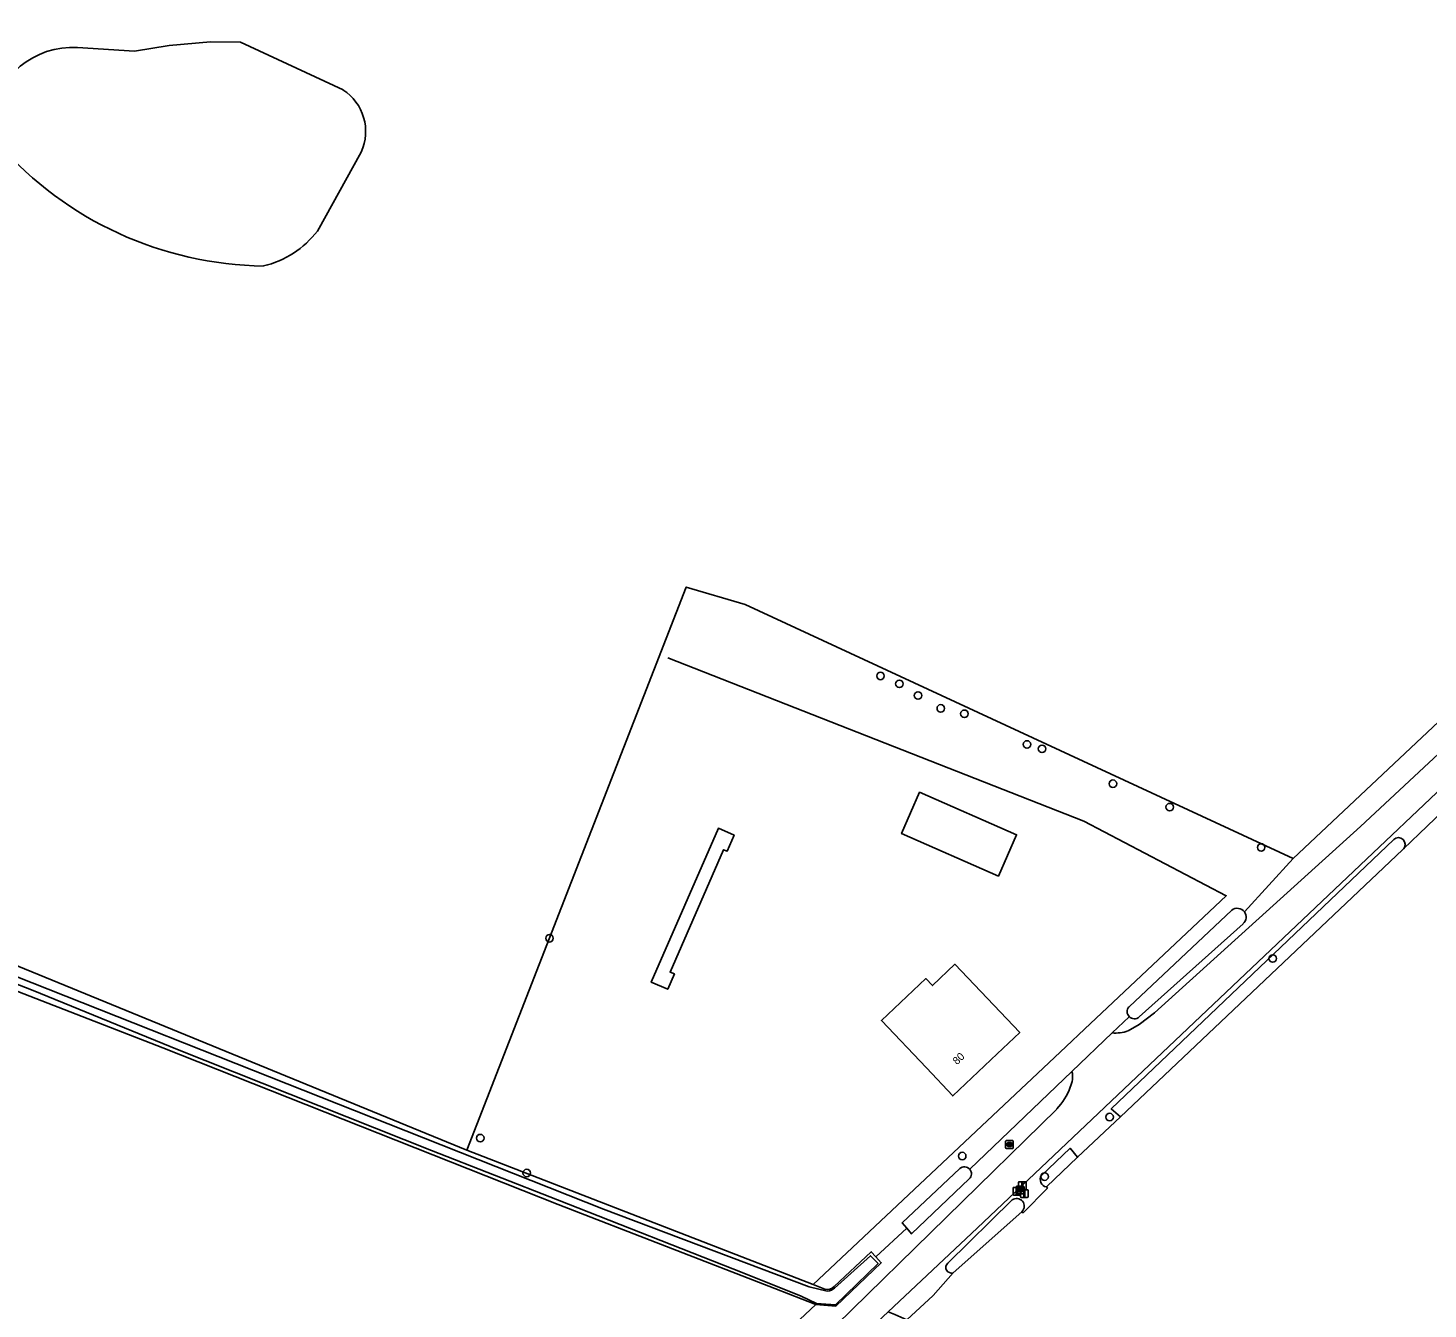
# Model space of a CAD drawing. Extents: x 155209 to 156748, y 385356 to 388487.
# Drawn here: x 155687.8 to 155870, y 387150.5 to 387317.3 of the extents above; entities that cross this region are included whole.
import ezdxf

# ---------------------------------------------------------------- set-up
doc = ezdxf.new("R2010")
doc.units = 0
for name, color, linetype in [('IMGEO_Afsluitpaal', 7, 'Continuous'), ('IMGEO_Berm_groen', 7, 'Continuous'), ('IMGEO_Boom', 7, 'Continuous'), ('IMGEO_Bouwland', 7, 'Continuous'), ('IMGEO_Brandkraan', 7, 'Continuous'), ('IMGEO_Erf', 7, 'Continuous'), ('IMGEO_Groenvoorziening', 7, 'Continuous'), ('IMGEO_Hek', 7, 'Continuous'), ('IMGEO_Meer_plas_ven_vijver', 7, 'Continuous'), ('IMGEO_Oever', 7, 'Continuous'), ('IMGEO_Pand', 7, 'Continuous'), ('IMGEO_Pand_nummerreeks', 7, 'Continuous'), ('IMGEO_Rijbaan_lokaal_onverhard', 7, 'Continuous'), ('IMGEO_Rioolput', 7, 'Continuous'), ('IMGEO_Waterloop', 7, 'Continuous')]:
    doc.layers.add(name, color=color, linetype=linetype)

msp = doc.modelspace()

# ---------------------------------------------------------------- linework, layer by layer
at = {"layer": 'IMGEO_Afsluitpaal'}
for p, q in [((155816.69, 387166.17), (155816.69, 387166.97)), ((155816.69, 387166.97), (155816.69, 387166.17)), ((155816.79, 387167.07), (155817.58, 387167.07)), ((155817.58, 387167.07), (155816.79, 387167.07)), ((155817.68, 387166.97), (155817.68, 387166.17)), ((155817.68, 387166.17), (155817.68, 387166.97)), ((155815.99, 387165.42), (155815.99, 387166.22)), ((155815.99, 387166.22), (155815.99, 387165.42)), ((155816.09, 387166.32), (155816.88, 387166.32)), ((155816.88, 387166.32), (155816.09, 387166.32)), ((155816.88, 387165.32), (155816.09, 387165.32)), ((155816.09, 387165.32), (155816.88, 387165.32)), ((155817.58, 387166.07), (155816.79, 387166.07)), ((155816.79, 387166.07), (155817.58, 387166.07)), ((155816.96, 387165.12), (155816.96, 387165.92)), ((155816.96, 387165.92), (155816.96, 387165.12)), ((155816.98, 387166.22), (155816.98, 387165.42)), ((155816.98, 387165.42), (155816.98, 387166.22)), ((155817.06, 387166.02), (155817.85, 387166.02)), ((155817.85, 387166.02), (155817.06, 387166.02)), ((155817.85, 387165.02), (155817.06, 387165.02)), ((155817.06, 387165.02), (155817.85, 387165.02)), ((155817.95, 387165.92), (155817.95, 387165.12)), ((155817.95, 387165.12), (155817.95, 387165.92))]:
    msp.add_line(p, q, dxfattribs=at)
for points in [[(155817.11, 387166.94), (155817.26, 387166.94), (155817.26, 387166.19), (155817.11, 387166.19), (155817.11, 387166.94)], [(155816.41, 387166.2), (155816.56, 387166.2), (155816.56, 387165.45), (155816.41, 387165.45), (155816.41, 387166.2)], [(155817.38, 387165.89), (155817.53, 387165.89), (155817.53, 387165.14), (155817.38, 387165.14), (155817.38, 387165.89)]]:
    msp.add_lwpolyline(points, dxfattribs=at)
for centre, start, end in [((155816.79, 387166.97), 90, 180), ((155816.79, 387166.97), 90, 180), ((155817.58, 387166.97), 0, 90), ((155817.58, 387166.97), 360, 90), ((155816.09, 387166.22), 90, 180), ((155816.09, 387166.22), 90, 180), ((155816.09, 387165.42), 180, 270), ((155816.09, 387165.42), 180, 270), ((155816.79, 387166.17), 180, 270), ((155816.79, 387166.17), 180, 270), ((155816.88, 387166.22), 0, 90), ((155816.88, 387166.22), 360, 90), ((155816.88, 387165.42), 270, 0), ((155816.88, 387165.42), 270, 0), ((155817.06, 387165.92), 90, 180), ((155817.06, 387165.92), 90, 180), ((155817.06, 387165.12), 180, 270), ((155817.06, 387165.12), 180, 270), ((155817.58, 387166.17), 270, 0), ((155817.58, 387166.17), 270, 0), ((155817.85, 387165.92), 0, 90), ((155817.85, 387165.92), 360, 90), ((155817.85, 387165.12), 270, 0), ((155817.85, 387165.12), 270, 0)]:
    msp.add_arc(centre, 0.1, start, end, dxfattribs=at)
at = {"layer": 'IMGEO_Berm_groen'}
for points in [[(155935.88, 387279.15), (155905.19, 387250), (155811.33, 387161.02), (155799.75, 387150.14), (155800.58, 387149.78), (155802.15, 387149.1), (155805.58, 387152.26), (155808.2, 387155.21)], [(155866.82, 387210.39), (155872.95, 387216.32), (155876.05, 387219.32)], [(155819.67, 387167.86), (155823.41, 387171.43), (155824.39, 387170.24), (155829.99, 387175.53), (155828.77, 387176.55), (155865.53, 387211.63)], [(155823.65, 387181.42), (155810.35, 387168.68)], [(155756.84, 387113.86), (155783.96, 387139.94), (155792.97, 387148.4), (155821.68, 387176.53)], [(155810.27, 387167.43), (155802.78, 387160.28), (155802.14, 387161.02), (155798.14, 387157.28), (155798.83, 387156.51), (155792.9, 387150.85), (155790.34, 387151.08), (155751.39, 387114.57), (155683.13, 387049.48), (155683.83, 387048.65), (155684.07, 387048.21)], [(155817.14, 387163.16), (155817.28, 387163.02), (155820.46, 387166.24), (155820.32, 387166.38)], [(155807.48, 387156.46), (155815.87, 387164.69)]]:
    msp.add_lwpolyline(points, dxfattribs=at)
for centre, radius, start, end in [((155866.13, 387210.96), 0.9, 320.4889, 131.6781), ((155820.51, 387180.73), 3.22, 334.7932, 12.2694), ((155815.75, 387182.12), 8.15, 316.7233, 340.2245), ((155809.65, 387168.09), 0.913, 313.1438, 40.1018), ((155820.52, 387167.36), 0.995, 149.3257, 258.1318), ((155816.46, 387163.89), 0.993, 312.9691, 126.4719), ((155807.97, 387155.91), 0.735, 131.7444, 287.6662)]:
    msp.add_arc(centre, radius, start, end, dxfattribs=at)
at = {"layer": 'IMGEO_Boom'}
for centre in [(155798.73, 387232.91), (155801.19, 387231.88), (155803.62, 387230.36), (155806.58, 387228.68), (155809.65, 387227.98), (155817.8, 387223.99), (155819.76, 387223.42), (155828.99, 387218.88), (155836.37, 387215.83), (155848.28, 387210.58), (155755.66, 387198.76), (155849.78, 387196.12), (155828.55, 387175.48), (155746.65, 387172.74), (155809.37, 387170.41), (155752.69, 387168.2), (155820.09, 387167.73)]:
    msp.add_circle(centre, 0.489, dxfattribs=at)
at = {"layer": 'IMGEO_Bouwland'}
for points in [[(155589.37, 387232.7), (155593.22, 387231.16), (155614.4, 387224.24), (155650.88, 387209.57), (155681.28, 387197.24), (155744.89, 387171.18), (155773.46, 387244.47), (155781.14, 387242.22), (155852.44, 387209.14), (155937.64, 387289.31), (155917.27, 387301.48), (155920.84, 387307.7), (155982.59, 387273.13), (155980.66, 387277.68), (155979.82, 387278.93), (155975.84, 387298.77), (155974.83, 387303.91), (155973.18, 387310.52), (155971.62, 387315.3), (155969.78, 387319.47), (155968.04, 387323.12), (155966.34, 387326.38), (155962.23, 387332.69), (155958.47, 387337.93)], [(155694.23, 387314.7), (155701.64, 387314.24), (155706.17, 387314.98), (155711.52, 387315.47), (155715.45, 387315.41), (155728.79, 387309.22)], [(155731.16, 387301.08), (155725.46, 387290.82)], [(155705.33, 387184.5), (155671.44, 387197.63), (155649.23, 387205.99), (155622.39, 387216.61), (155593.81, 387226.81), (155592, 387227.58), (155592.65, 387229.48), (155593.22, 387231.16), (155589.37, 387232.7)], [(155521.78, 387111.12), (155523.95, 387110.6), (155539.19, 387104.12), (155683.13, 387049.48), (155751.39, 387114.57), (155790.34, 387151.08), (155784.99, 387153.16), (155756.8, 387164.1), (155705.33, 387184.5)]]:
    msp.add_lwpolyline(points, dxfattribs=at)
msp.add_lwpolyline([(155983.31, 387261.26), (155977.7, 387264.44), (155946.02, 387282), (155934.44, 387274.3), (155908.63, 387250), (155876.05, 387219.32), (155872.95, 387216.32), (155866.82, 387210.39), (155866.68, 387210.25), (155829.99, 387175.53), (155824.39, 387170.24), (155820.32, 387166.38), (155820.46, 387166.24), (155817.28, 387163.02), (155817.14, 387163.16), (155808.2, 387155.21), (155805.58, 387152.26), (155802.15, 387149.1), (155805.27, 387147.74), (155854.95, 387128.34), (156000, 387072.11), (156012.96, 387067.09), (156020.54, 387071.32), (156019.65, 387072.07)], close=True, dxfattribs=at)
for centre, radius, start, end in [((155693.56, 387304.09), 10.63, 86.366, 172.8433), ((155725.21, 387303.77), 6.52, 335.6696, 56.8075), ((155719.04, 387332.92), 46.65, 221.362, 269.2722), ((155715.45, 387298.58), 12.66, 283.7044, 322.2261)]:
    msp.add_arc(centre, radius, start, end, dxfattribs=at)
at = {"layer": 'IMGEO_Brandkraan'}
for p, q in [((155816.41, 387165.55), (155816.41, 387166.41)), ((155816.48, 387166.48), (155817.33, 387166.48)), ((155817.33, 387165.48), (155816.48, 387165.48)), ((155816.66, 387165.97), (155816.66, 387165.99)), ((155817.1, 387165.94), (155816.7, 387165.94)), ((155816.71, 387166.02), (155817.1, 387166.02)), ((155816.89, 387166.26), (155816.92, 387166.26)), ((155816.92, 387165.7), (155816.89, 387165.7)), ((155817.15, 387165.99), (155817.15, 387165.97)), ((155817.41, 387166.41), (155817.41, 387165.55))]:
    msp.add_line(p, q, dxfattribs=at)
for points in [[(155816.41, 387165.55), (155816.41, 387166.41)], [(155816.48, 387166.48), (155817.33, 387166.48)], [(155817.33, 387165.48), (155816.48, 387165.48)], [(155817.41, 387166.41), (155817.41, 387165.55)]]:
    msp.add_lwpolyline(points, dxfattribs=at)
for centre, radius, start, end in [((155816.48, 387166.4), 0.0765, 91.552, 178.448), ((155816.48, 387166.4), 0.0765, 91.552, 178.448), ((155816.48, 387165.55), 0.0765, 181.552, 268.448), ((155816.48, 387165.55), 0.0765, 181.552, 268.448), ((155816.7, 387165.98), 0.0403, 85.8775, 175.7526), ((155816.7, 387165.97), 0.0366, 178.938, 274.7102), ((155817.11, 387165.98), 0.0386, 1.7309, 96.639), ((155817.11, 387165.98), 0.043, 264.8664, 352.4533), ((155817.33, 387166.4), 0.0765, 1.552, 88.448), ((155817.33, 387166.4), 0.0765, 1.552, 88.448), ((155817.33, 387165.55), 0.0765, 271.552, 358.448), ((155817.33, 387165.55), 0.0765, 271.552, 358.448)]:
    msp.add_arc(centre, radius, start, end, dxfattribs=at)
for centre, major_axis, ratio, start_param, end_param in [((155816.89, 387165.98), (-0.387, 0.002), 0.722429, 4.712389, 7.853982), ((155816.92, 387165.98), (-0.39, 0.002), 0.717154, 1.570796, 4.712389)]:
    msp.add_ellipse(centre, major_axis=major_axis, ratio=ratio, start_param=start_param, end_param=end_param, dxfattribs=at)
at = {"layer": 'IMGEO_Erf'}
for points in [[(155846.1, 387202.2), (155852.44, 387209.14), (155781.14, 387242.22), (155773.46, 387244.47), (155744.89, 387171.18), (155789.96, 387153.68), (155791.48, 387153.09)], [(155831.08, 387189.83), (155844.45, 387202.41)], [(155810.35, 387168.68), (155823.65, 387181.42), (155828.89, 387186.43), (155831.11, 387188.55)], [(155792.72, 387153.41), (155797.54, 387157.95), (155798.14, 387157.28), (155802.14, 387161.02), (155801.54, 387161.71), (155809.06, 387168.79)]]:
    msp.add_lwpolyline(points, dxfattribs=at)
for points in [[(155801.47, 387212.39), (155803.83, 387217.77), (155816.45, 387212.23), (155814.09, 387206.85)], [(155778.76, 387210.08), (155778.3, 387210.28), (155771.36, 387194.35), (155771.91, 387194.11), (155771.04, 387192.11), (155768.9, 387193.04), (155777.63, 387213.08), (155779.68, 387212.18)], [(155798.86, 387188.04), (155804.62, 387193.5), (155805.49, 387192.59), (155808.43, 387195.37), (155816.85, 387186.49), (155813.91, 387183.7), (155808.14, 387178.24), (155804.7, 387181.87)]]:
    msp.add_lwpolyline(points, close=True, dxfattribs=at)
for centre, radius, start, end in [((155845.17, 387201.52), 1.14, 36.0143, 129.1199), ((155831.77, 387189.21), 0.934, 138.2353, 224.6334), ((155809.65, 387168.09), 0.911, 40.1854, 130.1987), ((155791.84, 387154.25), 1.22, 252.7662, 316.1716)]:
    msp.add_arc(centre, radius, start, end, dxfattribs=at)
at = {"layer": 'IMGEO_Groenvoorziening'}
for points in [[(155920.84, 387307.7), (155917.27, 387301.48), (155937.64, 387289.31), (155852.44, 387209.14), (155846.1, 387202.2)], [(155830.95, 387186.71), (155832.39, 387187.53), (155834.38, 387189.06), (155861.21, 387213.3), (155900.6, 387250), (155933.07, 387281.51), (155935.61, 387283.98)], [(155845.92, 387200.65), (155832.4, 387188.52)], [(155831.11, 387188.55), (155828.89, 387186.43)]]:
    msp.add_lwpolyline(points, dxfattribs=at)
for centre, radius, start, end in [((155845.16, 387201.53), 1.15, 310.8618, 35.6282), ((155831.77, 387189.21), 0.934, 224.5906, 312.1287), ((155829.28, 387191.12), 4.71, 265.1674, 290.6484)]:
    msp.add_arc(centre, radius, start, end, dxfattribs=at)
at = {"layer": 'IMGEO_Hek'}
for points in [[(155826.07, 387187.67), (155843.73, 387204.29), (155825.2, 387213.99), (155771.05, 387235.25)], [(155822.13, 387183.95), (155826.07, 387187.67)], [(155789.96, 387153.68), (155822.13, 387183.95)]]:
    msp.add_lwpolyline(points, dxfattribs=at)
at = {"layer": 'IMGEO_Meer_plas_ven_vijver'}
for points in [[(155728.79, 387309.22), (155715.45, 387315.41), (155711.52, 387315.47), (155706.17, 387314.98), (155701.64, 387314.24), (155694.23, 387314.7)], [(155725.46, 387290.82), (155731.16, 387301.08)]]:
    msp.add_lwpolyline(points, dxfattribs=at)
for centre, radius, start, end in [((155693.56, 387304.09), 10.63, 86.366, 172.8433), ((155725.21, 387303.77), 6.52, 335.6696, 56.8075), ((155719.04, 387332.92), 46.65, 221.362, 269.2722), ((155715.45, 387298.58), 12.66, 283.7044, 322.2261)]:
    msp.add_arc(centre, radius, start, end, dxfattribs=at)
at = {"layer": 'IMGEO_Oever'}
for points in [[(155681.28, 387197.24), (155650.88, 387209.57), (155614.4, 387224.24), (155593.22, 387231.16), (155592.65, 387229.48), (155592, 387227.58), (155593.81, 387226.81), (155622.39, 387216.61), (155649.23, 387205.99), (155671.44, 387197.63), (155705.33, 387184.5), (155756.8, 387164.1), (155784.99, 387153.16), (155790.34, 387151.08), (155792.9, 387150.85), (155798.83, 387156.51), (155798.14, 387157.28), (155797.54, 387157.95), (155792.72, 387153.41)], [(155674.92, 387198.27), (155736.98, 387173.7), (155762.67, 387163.49), (155789.43, 387153.39), (155791.81, 387152.82), (155792.09, 387152.87), (155792.34, 387152.95), (155792.76, 387153.22), (155797.45, 387157.43), (155798.41, 387156.4), (155792.88, 387151.03), (155790.41, 387151.23), (155788.4, 387152.16), (155780.96, 387155.16), (155756.7, 387164.69), (155740.29, 387171.15), (155707.26, 387184.27), (155688.44, 387191.94), (155671.54, 387198.55)], [(155791.48, 387153.09), (155789.96, 387153.68), (155744.89, 387171.18), (155681.28, 387197.24)]]:
    msp.add_lwpolyline(points, dxfattribs=at)
msp.add_arc((155791.84, 387154.25), 1.22, 252.7662, 316.1716, dxfattribs=at)
at = {"layer": 'IMGEO_Pand'}
for points in [[(155814.09, 387206.85), (155816.45, 387212.23), (155803.83, 387217.77), (155801.47, 387212.39)], [(155777.63, 387213.08), (155768.9, 387193.04), (155771.04, 387192.11), (155771.91, 387194.11), (155771.36, 387194.35), (155778.3, 387210.28), (155778.76, 387210.08), (155779.68, 387212.18)], [(155804.7, 387181.87), (155808.14, 387178.24), (155813.91, 387183.7), (155816.85, 387186.49), (155808.43, 387195.37), (155805.49, 387192.59), (155804.62, 387193.5), (155798.86, 387188.04)]]:
    msp.add_lwpolyline(points, close=True, dxfattribs=at)
at = {"layer": 'IMGEO_Rijbaan_lokaal_onverhard'}
for points in [[(155935.61, 387283.98), (155933.07, 387281.51), (155900.6, 387250), (155861.21, 387213.3), (155834.38, 387189.06), (155832.39, 387187.53), (155830.95, 387186.71)], [(155821.68, 387176.53), (155792.97, 387148.4), (155783.96, 387139.94), (155756.84, 387113.86), (155698.02, 387058.78), (155700.72, 387056.35), (155701.85, 387057.41), (155730.2, 387083.45), (155741.87, 387094.48), (155760.02, 387111.9), (155774.91, 387126.23), (155788.34, 387139.42), (155799.75, 387150.14), (155811.33, 387161.02), (155905.19, 387250), (155935.88, 387279.15)], [(155828.89, 387186.43), (155823.65, 387181.42)]]:
    msp.add_lwpolyline(points, dxfattribs=at)
for centre, radius, start, end in [((155829.28, 387191.12), 4.71, 265.1674, 290.6484), ((155820.51, 387180.73), 3.22, 334.7932, 12.2694), ((155815.75, 387182.12), 8.15, 316.7233, 340.2245)]:
    msp.add_arc(centre, radius, start, end, dxfattribs=at)
at = {"layer": 'IMGEO_Rioolput'}
for p, q in [((155815.01, 387171.48), (155815.01, 387172.33)), ((155815.08, 387172.41), (155815.94, 387172.41)), ((155816.01, 387172.33), (155816.01, 387171.48)), ((155815.94, 387171.41), (155815.08, 387171.41)), ((155815.27, 387171.9), (155815.27, 387171.91)), ((155815.31, 387171.95), (155815.71, 387171.95)), ((155815.71, 387171.86), (155815.31, 387171.86)), ((155815.5, 387172.19), (155815.52, 387172.19)), ((155815.52, 387171.63), (155815.5, 387171.63)), ((155815.75, 387171.91), (155815.75, 387171.9))]:
    msp.add_line(p, q, dxfattribs=at)
for points in [[(155815.01, 387171.48), (155815.01, 387172.33)], [(155815.08, 387172.41), (155815.94, 387172.41)], [(155816.01, 387172.33), (155816.01, 387171.48)], [(155815.94, 387171.41), (155815.08, 387171.41)]]:
    msp.add_lwpolyline(points, dxfattribs=at)
for centre, radius, start, end in [((155815.09, 387172.33), 0.0765, 91.552, 178.448), ((155815.09, 387172.33), 0.0765, 91.552, 178.448), ((155815.93, 387172.33), 0.0765, 1.552, 88.448), ((155815.93, 387172.33), 0.0765, 1.552, 88.448), ((155815.09, 387171.48), 0.0765, 181.552, 268.448), ((155815.09, 387171.48), 0.0765, 181.552, 268.448), ((155815.31, 387171.91), 0.0403, 85.8775, 175.7526), ((155815.31, 387171.9), 0.0366, 178.938, 274.7102), ((155815.71, 387171.91), 0.0386, 1.7309, 96.639), ((155815.71, 387171.91), 0.043, 264.8664, 352.4533), ((155815.93, 387171.48), 0.0765, 271.552, 358.448), ((155815.93, 387171.48), 0.0765, 271.552, 358.448)]:
    msp.add_arc(centre, radius, start, end, dxfattribs=at)
for centre, major_axis, ratio, start_param, end_param in [((155815.5, 387171.91), (-0.387, 0.002), 0.722429, 4.712389, 7.853982), ((155815.52, 387171.91), (-0.39, 0.002), 0.717154, 1.570796, 4.712389)]:
    msp.add_ellipse(centre, major_axis=major_axis, ratio=ratio, start_param=start_param, end_param=end_param, dxfattribs=at)
at = {"layer": 'IMGEO_Waterloop'}
for points in [[(155865.53, 387211.63), (155828.77, 387176.55), (155829.99, 387175.53), (155866.68, 387210.25), (155866.82, 387210.39)], [(155844.45, 387202.41), (155831.08, 387189.83)], [(155832.4, 387188.52), (155845.92, 387200.65)], [(155671.54, 387198.55), (155688.44, 387191.94), (155707.26, 387184.27), (155740.29, 387171.15), (155756.7, 387164.69), (155780.96, 387155.16), (155788.4, 387152.16), (155790.41, 387151.23), (155792.88, 387151.03), (155798.41, 387156.4), (155797.45, 387157.43), (155792.76, 387153.22), (155792.34, 387152.95), (155792.09, 387152.87), (155791.81, 387152.82), (155789.43, 387153.39), (155762.67, 387163.49), (155736.98, 387173.7), (155674.92, 387198.27)], [(155820.32, 387166.38), (155824.39, 387170.24), (155823.41, 387171.43), (155819.67, 387167.86)], [(155809.06, 387168.79), (155801.54, 387161.71), (155802.14, 387161.02), (155802.78, 387160.28), (155810.27, 387167.43)], [(155815.87, 387164.69), (155807.48, 387156.46)], [(155808.2, 387155.21), (155817.14, 387163.16)]]:
    msp.add_lwpolyline(points, dxfattribs=at)
for centre, radius, start, end in [((155866.13, 387210.96), 0.9, 320.4889, 131.6781), ((155845.17, 387201.52), 1.14, 36.0143, 129.1199), ((155845.16, 387201.53), 1.15, 310.8618, 35.6282), ((155831.77, 387189.21), 0.934, 138.2353, 224.6334), ((155831.77, 387189.21), 0.934, 224.5906, 312.1287), ((155809.65, 387168.09), 0.911, 40.1854, 130.1987), ((155809.65, 387168.09), 0.913, 313.1438, 40.1018), ((155820.52, 387167.36), 0.995, 149.3257, 258.1318), ((155816.46, 387163.89), 0.993, 312.9691, 126.4719), ((155807.97, 387155.91), 0.735, 131.7444, 287.6662)]:
    msp.add_arc(centre, radius, start, end, dxfattribs=at)

# ---------------------------------------------------------------- texts
at = {"layer": 'IMGEO_Pand_nummerreeks'}
msp.add_text('80', height=1, rotation=43.4392, dxfattribs=at).set_placement((155808.69, 387182.23))

doc.saveas('drawing.dxf')
